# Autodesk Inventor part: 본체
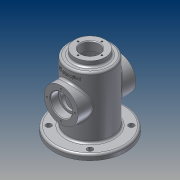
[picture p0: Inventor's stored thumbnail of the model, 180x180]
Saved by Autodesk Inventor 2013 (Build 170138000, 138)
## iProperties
Created: 2014-12
Part Number: 본체
Material: 알루미늄 6061
Document SubType Name: Modeling
Designer: H1
Mass: 478.837 g
Surface Area: 605.5 cm^2
Volume: 176.693 cm^3
Density: 2.71 g/cm^3
Author: H1
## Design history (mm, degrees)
sketch "스케치1"
  geometry: L1 (0, -55)-(0, 43); L2 (-27.5, -55)-(-27.5, 38); L3 (-27.5, 38)-(0, 38); L4 (0, 38)-(0, 43); L5 (-32.5, 43)-(-32.5, -47); L6 (-32.5, -47)-(-52.5, -47); L7 (-52.5, -47)-(-52.5, -55); L8 (-52.5, -55)-(-27.5, -55); L9 (0, 43)-(-32.5, 43); 2 further points
  constraints: 18 end point, 5 parallel, 2 perpendicular, 1 collinear, 1 horizontal alignment, 1 midpoint, 1 point on line, 1 vertical, 1 vertical alignment
  dimensions: "d0" = 98 distance of L1.start L1.end; "d1" = 55 distance of point (0, 0) L1.start; "d3" = 65 diameter of L5 L1; "d4" = 55 diameter of L2 L1; "d5" = 5 distance between parallel lines of L3 L9; "d6" = 105 diameter of L7 L1; "d7" = 8 distance between parallel lines of L6 L8; "d8" = 5 distance between parallel lines of L5 L2 (derived); "d9" = 25 distance of L7.end L2.start (derived)
revolve "회전1" sketch "스케치1" stored, may be unused: angle "d10" = 90 deg
node "작업 평면1"
sketch "스케치2"
  geometry: C1 r 22.5 at (0, 0); C2 r 13.5 at (0, 0); A1 r 17.5 centre (0, 0) between (17.5, 0) and (-17.5, 0); 3 further points
  constraints: 4 point on circle, 3 centre point, 3 coincident
  dimensions: "d12" = 45 diameter of C1; "d13" = 27 diameter of C2; "d14" = 35 diameter of A1
extrude "돌출1" join sketch "스케치2" stored distance "d15" = 10; taper "d16" = 0 deg
extrude "돌출2" cut sketch "스케치2" stored distance "d17" = 10; taper "d18" = 0 deg
hole "구멍1" sketch "스케치2" diameter "d19" = 2.459; stored, may be unused: countersink angle "d23" = 90 deg, drill point angle "d25" = 118 deg; dims "d20" = 6, "d21" = 4, "d22" = 2, "d24" = 8
node "작업 평면2"
sketch "스케치3"
  geometry: C1 r 25 at (0, 0); 1 further point
  constraints: 1 centre point, 1 coincident
  dimensions: "d27" = 50 diameter of C1
extrude "돌출3" join sketch "스케치3" stored distance "d28" = 10; taper "d29" = 0 deg
hole "구멍2" diameter "d32" = 25; stored, may be unused: countersink angle "d36" = 90 deg, drill point angle "d38" = 118 deg; dims "d30" = 10, "d31" = 10, "d33" = 6, "d34" = 32, "d35" = 12, "d37" = 30
sketch "스케치4"
  geometry: A1 r 20.5 centre (0, 0) between (0, 20.5) and (20.5, 0); 3 further points
  constraints: 4 point on circle, 1 centre point, 1 coincident
  dimensions: "d39" = 41 diameter of A1
hole "구멍3" sketch "스케치4" at (0, 20.5), (20.5, 0), (0, -20.5), (-20.5, 0) diameter "d40" = 2.459; stored, may be unused: countersink angle "d44" = 90 deg, drill point angle "d46" = 118 deg; dims "d41" = 6, "d42" = 32, "d43" = 12, "d45" = 8
node "작업 평면3"
sketch "스케치5"
  geometry: L1 (43, -32.5)-(43, 32.5) reference; L2 (-47, 32.5)-(43, 32.5) reference; 2 further points
  constraints: 1 other
  dimensions: "d59" = 9 distance from line of point (34, 0) L1; "d60" = 32.5 distance from line of point (34, 0) L2
feature "엠보싱1" sketch "스케치5" dims "d48" = 1, "d49" = 0
sketch "스케치6"
  geometry: L1 (0, 0)-(30.406, 30.406); L2 (0, 0)-(43, 0); C1 r 43 at (0, 0); C2 r 4 at (30.406, 30.406); 1 further point
  constraints: 4 end point, 2 centre point, 2 coincident, 1 equal length, 1 horizontal
  dimensions: "d50" = 86 diameter of C1; "d51" = 43 distance of L1.start L1.end; "d52" = 45 deg angle of L2 L1; "d53" = 8 diameter of C2
extrude "돌출4" cut sketch "스케치6" stored distance "d54" = 10; taper "d55" = 0 deg
fillet "모깎기1" dims "d61" = 3
fillet "모깎기2" dims "d62" = 3
chamfer "모따기1" distance "d63" = 1; stored, may be unused: second distance "d64" = 2, angle "d65" = 45 deg
fillet "모깎기3" dims "d66" = 0.3
node "솔리드1"
mirror "대칭1"
mirror "대칭2"
mirror "대칭3"
pattern_circular "원형 패턴1" dims angle "d57" = 360 deg
other parameters: "d11" = 51, "d26" = 42.5, "d47" = 32.5
